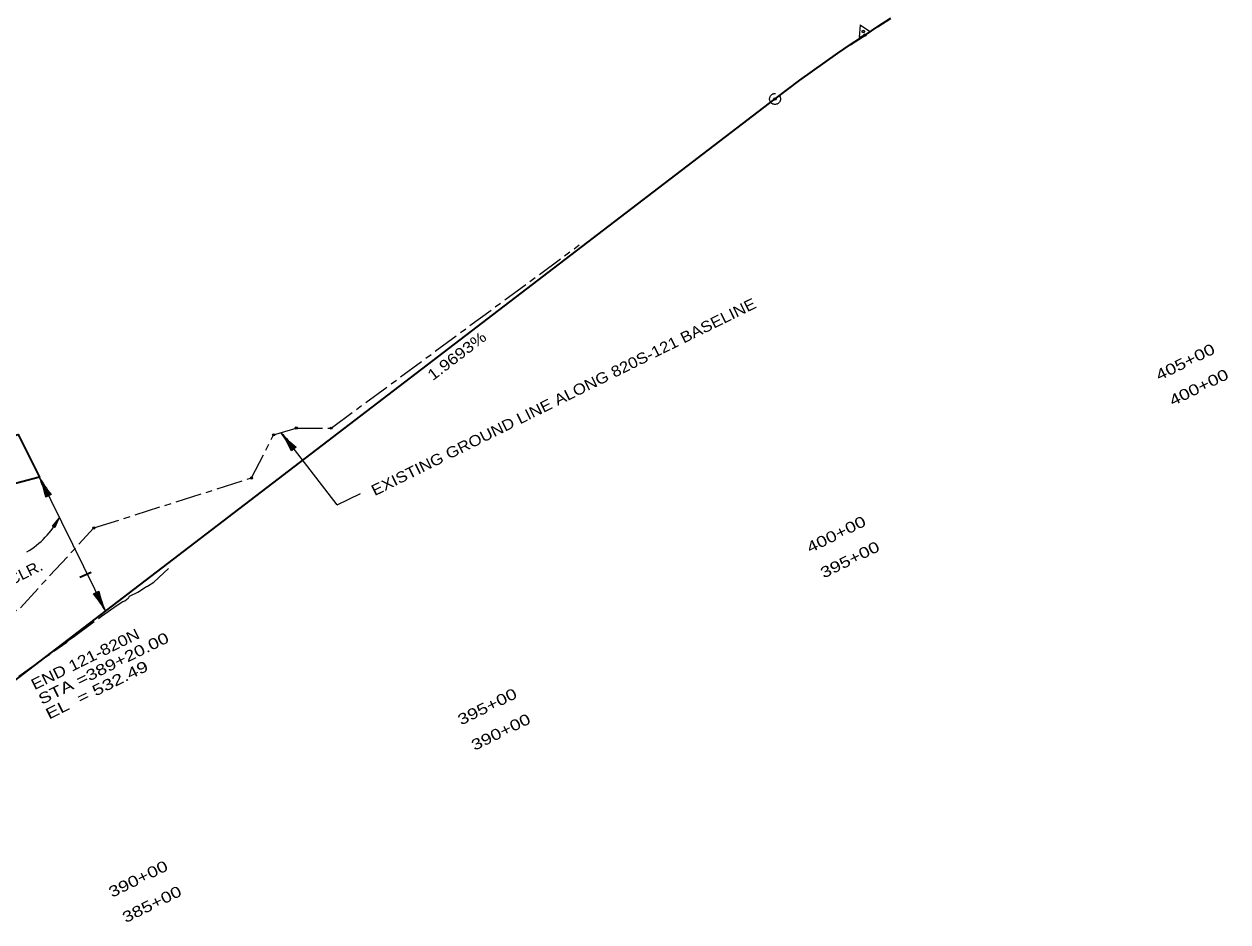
# Model space of a CAD drawing. Extents: x 2356431 to 2371438, y 6972864 to 6982525.
# Drawn here: x 2367303 to 2368849, y 6977741 to 6978894 of the extents above; entities that cross this region are included whole.
import ezdxf
from ezdxf.enums import TextEntityAlignment as Align

# ---------------------------------------------------------------- set-up
doc = ezdxf.new("R2010")
doc.units = 0
doc.header["$LTSCALE"] = 5.6
doc.header["$PDMODE"] = 32
doc.header["$PDSIZE"] = 2.8
doc.linetypes.add('DASH_DOUBLE_DOT', pattern=[9.2, 5, -1.2, 0.3, -1.2, 0.3, -1.2])
doc.linetypes.add('LONG_DASH_SHORT_DASH', pattern=[9.9, 6, -1.2, 1.5, -1.2])
for name, color, linetype, lineweight in [('1', 7, 'Continuous', 25), ('2', 7, 'Continuous', 35), ('44', 7, 'Continuous', 13), ('52', 7, 'Continuous', 25), ('53', 7, 'Continuous', 13), ('55', 7, 'Continuous', 13), ('61', 7, 'Continuous', 13)]:
    doc.layers.add(name, color=color, linetype=linetype, lineweight=lineweight)

msp = doc.modelspace()

# ---------------------------------------------------------------- linework, layer by layer
at = {"layer": '1', "lineweight": 13}
for p, q in [((2367322.19, 6978311.779), (2367407.147, 6978139.636)), ((2367334.09, 6978287.96), (2367322.969, 6978310.495)), ((2367333.193, 6978287.519), (2367325.572, 6978302.96)), ((2367332.296, 6978287.076), (2367327.992, 6978295.796)), ((2367334.987, 6978288.403), (2367328.481, 6978301.586)), ((2367335.884, 6978288.846), (2367332.098, 6978296.517)), ((2367331.4, 6978286.633), (2367329.291, 6978290.905)), ((2367337.408, 6978289.598), (2367330.539, 6978286.208)), ((2367336.779, 6978289.288), (2367335.377, 6978292.131)), ((2367391.929, 6978161.816), (2367398.798, 6978165.206)), ((2367392.556, 6978162.126), (2367393.96, 6978159.282)), ((2367393.453, 6978162.569), (2367397.239, 6978154.898)), ((2367394.35, 6978163.011), (2367400.856, 6978149.828)), ((2367395.247, 6978163.453), (2367406.368, 6978140.919)), ((2367396.144, 6978163.896), (2367403.765, 6978148.455)), ((2367397.04, 6978164.339), (2367401.344, 6978155.618)), ((2367397.937, 6978164.782), (2367400.046, 6978160.509))]:
    msp.add_line(p, q, dxfattribs=at)
at = {"layer": '1', "lineweight": 35}
msp.add_lwpolyline([(2367212.518, 6978325.882), (2367249.95, 6978354.503), (2367295.068, 6978366.623), (2367322.19, 6978311.779), (2367276.972, 6978299.633), (2367239.664, 6978271.105)], close=True, dxfattribs=at)
at = {"layer": '1', "lineweight": 13}
for centre, radius, start, end in [((2367189.662, 6978254.362), 144.431, 12.73827, 23.42432), ((2367448.376, 6978382.046), 144.431, 209.11143, 219.79748), ((2367249.406, 6978311.491), 111.172, 300.56226, 332.01735), ((2367280.96, 6978069.369), 144.431, 29.11143, 39.79748), ((2367539.675, 6978197.053), 144.431, 192.73827, 203.42432)]:
    msp.add_arc(centre, radius, start, end, dxfattribs=at)
at = {"layer": '2'}
for p, q in [((2368364.5, 6978867.368), (2368381.003, 6978878.384)), ((2368331.757, 6978844.796), (2368348.084, 6978856.172)), ((2368299.368, 6978821.509), (2368315.518, 6978833.242)), ((2366966.766, 6977802.834), (2368267.334, 6978797.502))]:
    msp.add_line(p, q, dxfattribs=at)
at = {"layer": '44'}
for p, q in [((2367649.147, 6978347.913), (2367633.849, 6978367.85)), ((2367704.946, 6978276.164), (2367635.203, 6978366.166)), ((2367648.351, 6978347.303), (2367637.87, 6978360.967)), ((2367649.94, 6978348.521), (2367640.991, 6978360.183)), ((2367650.732, 6978349.13), (2367645.526, 6978355.917)), ((2367647.558, 6978346.696), (2367641.64, 6978354.411)), ((2367646.766, 6978346.086), (2367643.866, 6978349.866)), ((2367652.081, 6978350.164), (2367646.003, 6978345.502)), ((2367651.526, 6978349.739), (2367649.596, 6978352.253)), ((2367704.946, 6978276.164), (2367734.793, 6978290.895))]:
    msp.add_line(p, q, dxfattribs=at)
for centre, start, end in [((2367742.925, 6978462.451), 220.33959, 231.02564), ((2367514.024, 6978286.834), 23.96642, 34.65247)]:
    msp.add_arc(centre, 144.431, start, end, dxfattribs=at)
at = {"layer": '52', "linetype": 'LONG_DASH_SHORT_DASH'}
for points in [[(2367652.293, 6978374.932), (2367697.016, 6978374.702), (2368015.776, 6978610.084)], [(2367392.228, 6978246.582), (2367594.713, 6978310.829), (2367623.175, 6978366.14), (2367652.293, 6978374.932)], [(2366925.324, 6977904.629), (2367297.777, 6978144.207), (2367392.228, 6978246.582)], [(2367431.94, 6978152.956), (2367436.309, 6978156.397), (2367436.997, 6978157.375), (2367438.178, 6978159.049), (2367448.639, 6978164.018), (2367459.923, 6978171.343), (2367460.813, 6978171.438), (2367461.259, 6978171.617), (2367469.234, 6978177.015), (2367488.263, 6978194.428)], [(2367295.987, 6978056.276), (2367340.997, 6978088.494), (2367357.371, 6978100.032), (2367360.374, 6978103.055), (2367365.549, 6978106.284), (2367401.864, 6978133.117), (2367422.351, 6978147.237), (2367429.3, 6978151.956), (2367431.94, 6978152.956)]]:
    msp.add_lwpolyline(points, dxfattribs=at)
at = {"layer": '52'}
for p in [(2367652.293, 6978374.932), (2367697.016, 6978374.702), (2367623.175, 6978366.14), (2367594.713, 6978310.829), (2367392.228, 6978246.582)]:
    msp.add_point(p, dxfattribs=at)
at = {"layer": '53', "lineweight": 35}
for p, q in [((2368348.084, 6978856.172), (2368364.5, 6978867.368)), ((2368381.003, 6978878.384), (2368382.921, 6978879.648)), ((2368315.518, 6978833.242), (2368331.757, 6978844.796))]:
    msp.add_line(p, q, dxfattribs=at)
at = {"layer": '53', "linetype": 'DASH_DOUBLE_DOT', "lineweight": 35}
msp.add_line((2367373.982, 6978183.362), (2367388.735, 6978189.896), dxfattribs=at)
at = {"layer": '53', "lineweight": 35}
for points in [[(2368382.921, 6978879.648), (2368399.524, 6978890.465), (2368416.215, 6978901.102)], [(2368267.333, 6978797.502), (2368283.306, 6978809.595), (2368299.368, 6978821.509)]]:
    msp.add_lwpolyline(points, dxfattribs=at)
at = {"layer": '53'}
for p in [(2368382.921, 6978879.648), (2368267.333, 6978797.502)]:
    msp.add_point(p, dxfattribs=at)
at = {"layer": '55'}
for p, q in [((2367342.133, 6978247.033), (2367338.887, 6978249.067)), ((2367339.295, 6978248.812), (2367340.559, 6978250.831)), ((2367339.718, 6978248.546), (2367342.301, 6978252.666)), ((2367340.142, 6978248.281), (2367344.715, 6978255.575)), ((2367340.565, 6978248.016), (2367347.239, 6978258.661)), ((2367340.99, 6978247.75), (2367344.892, 6978253.977)), ((2367341.413, 6978247.484), (2367343.684, 6978251.108)), ((2367341.836, 6978247.219), (2367342.679, 6978248.562))]:
    msp.add_line(p, q, dxfattribs=at)
for centre, start, end in [((2367288.373, 6978300.675), 314.38617, 325.07222), ((2367410.594, 6978224.053), 150.75933, 161.44538)]:
    msp.add_arc(centre, 72.216, start, end, dxfattribs=at)
at = {"layer": '61', "linetype": 'LONG_DASH_SHORT_DASH'}
for p, q in [((2368376.561, 6978892.56), (2368375.507, 6978876.439)), ((2368375.507, 6978876.439), (2368389.999, 6978883.59)), ((2368376.561, 6978892.56), (2368389.999, 6978883.59))]:
    msp.add_line(p, q, dxfattribs=at)
for centre, radius in [((2368380.681, 6978884.189), 1.5), ((2368267.334, 6978797.502), 7)]:
    msp.add_circle(centre, radius, dxfattribs=at)

# ---------------------------------------------------------------- texts
at = {"layer": '1', "width": 1.1}
msp.add_text('MIN.CLR.', height=14, rotation=26.268, dxfattribs=at).set_placement((2367287.637, 6978173.296), align=Align.CENTER)
at = {"layer": '2', "width": 1.15}
msp.add_text('EXISTING GROUND LINE ALONG 820S-121 BASELINE', height=14, rotation=26.268, dxfattribs=at).set_placement((2367998.761, 6978408.648), align=Align.CENTER)
at = {"layer": '2', "width": 1.2}
msp.add_text('1.9693%', height=14, rotation=37.409, dxfattribs=at).set_placement((2367827.589, 6978435.116))
at = {"layer": '53', "width": 1.3}
for s, p in [('405+00', (2368797.411, 6978453.475)), ('400+00', (2368814.857, 6978420.878)), ('400+00', (2368348.973, 6978232.156)), ('395+00', (2368366.568, 6978199.633)), ('395+00', (2367900.684, 6978010.911)), ('390+00', (2367918.131, 6977978.314)), ('390+00', (2367452.247, 6977789.593)), ('385+00', (2367469.793, 6977757.045))]:
    msp.add_text(s, height=14, rotation=26.268, dxfattribs=at).set_placement(p, align=Align.CENTER)
at = {"layer": '53'}
for s, width, p in [('END 121-820N', 1.2, (2367315.907, 6978038.095)), ('STA =389+20.00', 1.3, (2367325.2, 6978019.264)), ('EL  = 532.49', 1.35, (2367334.494, 6978000.433))]:
    msp.add_text(s, height=14, rotation=26.268, dxfattribs=dict(at, width=width)).set_placement(p)

doc.saveas('drawing.dxf')
